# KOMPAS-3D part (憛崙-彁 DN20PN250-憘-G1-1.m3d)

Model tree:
1. Объединить компоненты:1  (labels: СЕНС-ПР DN20PN250-G1-1)
2. Эскиз:1
3. Операция выдавливания:1
     Расстояние 1 = 14; Расстояние 2 = 55
4. Фаска:1
     Угол = 45; Длина 1 = 2; Длина 2 = 2

Referenced files in D:\Савин\!СЕНСОР\3D для заказчика\!Новый перечень\СЕНС-ПР\4. СЕНС-ПР-PN250\DN20\: СЕНС-ПР DN20PN250-G1-1.a3d
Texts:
  СЕНС-ПР DN20PN250-СВ-G1-1
  ООО НПП Сенсор
  СЕНС-ПР DN20PN250-G1-1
